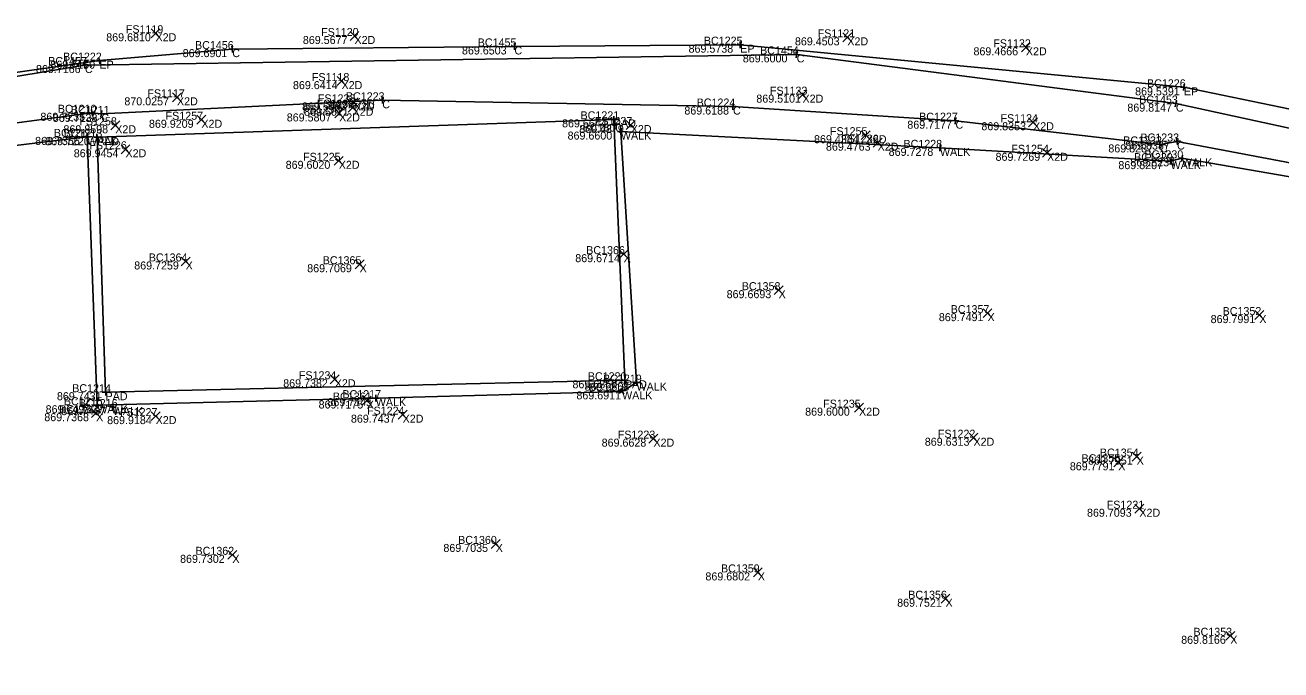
# Model space of a CAD drawing. Extents: x 1479425 to 1480294, y 379351 to 380102.
# Drawn here: x 1479629.1 to 1479638.52, y 379873.44 to 379878.28 of the extents above; entities that cross this region are included whole.
import ezdxf

# ---------------------------------------------------------------- set-up
doc = ezdxf.new("R2010")
doc.units = 0
for name, color, linetype in [('PV_X_Curb', 7, 'Continuous'), ('PV_X_Walk', 7, 'Continuous'), ('RD_X_Concrete_Pad', 7, 'Continuous'), ('SV_X_Random_Point', 7, 'Continuous'), ('SV_X_Shot_Marker', 7, 'Continuous'), ('SV_X_Text_Comment', 7, 'Continuous'), ('SV_X_Text_Elevation', 7, 'Continuous'), ('SV_X_Text_Name', 7, 'Continuous')]:
    doc.layers.add(name, color=color, linetype=linetype)

msp = doc.modelspace()

# ---------------------------------------------------------------- linework, layer by layer
at = {"layer": 'PV_X_Curb'}
for points in [[(1479547.645, 379857.8163), (1479566.743, 379862.6799), (1479585.84, 379867.6329), (1479595.941, 379870.2102), (1479610.1511, 379873.8057), (1479614.8317, 379874.9648), (1479619.4026, 379876.1566), (1479624.8139, 379877.3196), (1479629.6596, 379878.0099), (1479630.6556, 379878.0962), (1479632.7718, 379878.1163), (1479634.4649, 379878.1296), (1479637.7922, 379877.8099), (1479639.1613, 379877.5269), (1479644.7184, 379876.0341), (1479650.0207, 379873.0081)], [(1479674.4002, 379850.8088), (1479663.165, 379861.2618), (1479660.4814, 379863.897), (1479660.3417, 379864.0048), (1479659.4756, 379864.8615), (1479657.9728, 379866.276), (1479656.299, 379867.8605), (1479655.4781, 379868.4849), (1479655.3936, 379868.553), (1479653.3405, 379870.3718), (1479649.8028, 379873.0366), (1479644.8359, 379875.8815), (1479640.9714, 379876.9839), (1479637.7316, 379877.6879), (1479634.8886, 379878.0569), (1479629.5507, 379877.9769), (1479626.9417, 379877.5496), (1479624.927, 379877.2311), (1479623.2196, 379876.8713), (1479619.5522, 379875.9957), (1479615.007, 379874.7968)], [(1479547.62, 379857.3293), (1479567.188, 379862.296), (1479585.958, 379867.1036), (1479596.074, 379869.8004), (1479610.1997, 379873.3276), (1479614.9812, 379874.5289), (1479617.4646, 379875.192), (1479619.4347, 379875.7199), (1479619.5957, 379875.717), (1479622.3222, 379876.3413), (1479624.8041, 379876.8646), (1479627.2818, 379877.3077), (1479629.6031, 379877.6193), (1479629.6735, 379877.6107), (1479631.7805, 379877.7128), (1479634.4106, 379877.6659), (1479636.0794, 379877.5598), (1479637.6114, 379877.382), (1479637.7407, 379877.4038), (1479639.5316, 379877.066), (1479644.5411, 379875.6244), (1479649.735, 379872.6614)]]:
    msp.add_lwpolyline(points, dxfattribs=at)
at = {"layer": 'PV_X_Walk'}
msp.add_lwpolyline([(1479648.689, 379868.2743), (1479647.1434, 379869.696), (1479647.0829, 379869.7025), (1479645.8749, 379870.8123), (1479644.5568, 379872.0701), (1479644.4905, 379872.1256), (1479643.2259, 379873.2388), (1479641.9481, 379874.5109), (1479641.8756, 379874.5801), (1479640.4852, 379875.8117), (1479639.2266, 379877.0297), (1479637.7773, 379877.2778), (1479637.6922, 379877.2566), (1479635.9625, 379877.3562), (1479633.5699, 379877.4783), (1479633.687, 379875.5967), (1479633.579, 379875.5311), (1479631.7319, 379875.4802), (1479629.6435, 379875.4272), (1479629.5678, 379877.4383), (1479627.2312, 379877.1555), (1479624.9702, 379876.7386), (1479624.8804, 379876.715), (1479622.4184, 379876.2221)], dxfattribs=at)
at = {"layer": 'RD_X_Concrete_Pad'}
msp.add_lwpolyline([(1479629.6418, 379877.4358), (1479629.7055, 379875.5248), (1479633.5999, 379875.6143), (1479633.5176, 379877.57)], close=True, dxfattribs=at)
at = {"layer": 'SV_X_Random_Point'}
for p, q in [((1479630.0467, 379878.1818), (1479630.1133, 379878.2486)), ((1479630.0467, 379878.2486), (1479630.1133, 379878.1818)), ((1479631.5387, 379878.1614), (1479631.6053, 379878.2282)), ((1479631.5387, 379878.2282), (1479631.6053, 379878.1614)), ((1479635.2347, 379878.1512), (1479635.3013, 379878.218)), ((1479635.2347, 379878.218), (1479635.3013, 379878.1512)), ((1479636.5737, 379878.0765), (1479636.6403, 379878.1433)), ((1479636.5737, 379878.1433), (1479636.6403, 379878.0765)), ((1479631.4417, 379877.8231), (1479631.5083, 379877.8899)), ((1479631.4417, 379877.8899), (1479631.5083, 379877.8231)), ((1479630.2077, 379877.7017), (1479630.2743, 379877.7685)), ((1479630.2077, 379877.7685), (1479630.2743, 379877.7017)), ((1479634.8987, 379877.7217), (1479634.9653, 379877.7885)), ((1479634.8987, 379877.7885), (1479634.9653, 379877.7217)), ((1479631.4237, 379877.5809), (1479631.4903, 379877.6477)), ((1479631.4237, 379877.6477), (1479631.4903, 379877.5809)), ((1479631.5247, 379877.6236), (1479631.5913, 379877.6904)), ((1479631.5247, 379877.6904), (1479631.5913, 379877.6236)), ((1479631.5337, 379877.6636), (1479631.6003, 379877.7304)), ((1479631.5337, 379877.7304), (1479631.6003, 379877.6636)), ((1479629.7447, 379877.4922), (1479629.8113, 379877.559)), ((1479629.7447, 379877.559), (1479629.8113, 379877.4922)), ((1479630.3907, 379877.5333), (1479630.4573, 379877.6001)), ((1479630.3907, 379877.6001), (1479630.4573, 379877.5333)), ((1479633.6107, 379877.4939), (1479633.6773, 379877.5607)), ((1479633.6107, 379877.5607), (1479633.6773, 379877.4939)), ((1479636.6277, 379877.5149), (1479636.6943, 379877.5817)), ((1479636.6277, 379877.5817), (1479636.6943, 379877.5149)), ((1479635.3727, 379877.4177), (1479635.4393, 379877.4845)), ((1479635.3727, 379877.4845), (1479635.4393, 379877.4177)), ((1479629.8217, 379877.3123), (1479629.8883, 379877.3791)), ((1479629.8217, 379877.3791), (1479629.8883, 379877.3123)), ((1479635.4617, 379877.3618), (1479635.5283, 379877.4286)), ((1479635.4617, 379877.4286), (1479635.5283, 379877.3618)), ((1479631.4207, 379877.2258), (1479631.4873, 379877.2926)), ((1479631.4207, 379877.2926), (1479631.4873, 379877.2258)), ((1479636.7327, 379877.2857), (1479636.7993, 379877.3525)), ((1479636.7327, 379877.3525), (1479636.7993, 379877.2857)), ((1479630.2726, 379876.4713), (1479630.3392, 379876.5381)), ((1479630.2726, 379876.5381), (1479630.3392, 379876.4713)), ((1479631.5774, 379876.4505), (1479631.644, 379876.5173)), ((1479631.5774, 379876.5173), (1479631.644, 379876.4505)), ((1479633.5572, 379876.526), (1479633.6238, 379876.5928)), ((1479633.5572, 379876.5928), (1479633.6238, 379876.526)), ((1479634.7194, 379876.2561), (1479634.786, 379876.3229)), ((1479634.7194, 379876.3229), (1479634.786, 379876.2561)), ((1479636.2858, 379876.084), (1479636.3524, 379876.1508)), ((1479636.2858, 379876.1508), (1479636.3524, 379876.084)), ((1479638.3245, 379876.0694), (1479638.3911, 379876.1362)), ((1479638.3245, 379876.1362), (1479638.3911, 379876.0694)), ((1479631.3907, 379875.5884), (1479631.4573, 379875.6552)), ((1479631.3907, 379875.6552), (1479631.4573, 379875.5884)), ((1479631.6312, 379875.4292), (1479631.6978, 379875.496)), ((1479631.6312, 379875.496), (1479631.6978, 379875.4292)), ((1479629.6012, 379875.3342), (1479629.6678, 379875.401)), ((1479629.6012, 379875.401), (1479629.6678, 379875.3342)), ((1479631.8997, 379875.3229), (1479631.9663, 379875.3897)), ((1479631.8997, 379875.3897), (1479631.9663, 379875.3229)), ((1479635.3227, 379875.3755), (1479635.3893, 379875.4423)), ((1479635.3227, 379875.4423), (1479635.3893, 379875.3755)), ((1479630.0477, 379875.3121), (1479630.1143, 379875.3789)), ((1479630.0477, 379875.3789), (1479630.1143, 379875.3121)), ((1479633.7807, 379875.1434), (1479633.8473, 379875.2102)), ((1479633.7807, 379875.2102), (1479633.8473, 379875.1434)), ((1479636.1807, 379875.1501), (1479636.2473, 379875.2169)), ((1479636.1807, 379875.2169), (1479636.2473, 379875.1501)), ((1479637.2666, 379874.9663), (1479637.3332, 379875.0331)), ((1479637.2666, 379875.0331), (1479637.3332, 379874.9663)), ((1479637.4044, 379875.0089), (1479637.471, 379875.0757)), ((1479637.4044, 379875.0757), (1479637.471, 379875.0089)), ((1479637.4247, 379874.618), (1479637.4913, 379874.6848)), ((1479637.4247, 379874.6848), (1479637.4913, 379874.618)), ((1479632.5982, 379874.3542), (1479632.6648, 379874.421)), ((1479632.5982, 379874.421), (1479632.6648, 379874.3542)), ((1479630.623, 379874.2725), (1479630.6896, 379874.3393)), ((1479630.623, 379874.3393), (1479630.6896, 379874.2725)), ((1479634.5637, 379874.1407), (1479634.6303, 379874.2075)), ((1479634.5637, 379874.2075), (1479634.6303, 379874.1407)), ((1479635.971, 379873.9434), (1479636.0376, 379874.0102)), ((1479635.971, 379874.0102), (1479636.0376, 379873.9434)), ((1479638.1061, 379873.6656), (1479638.1727, 379873.7324)), ((1479638.1061, 379873.7324), (1479638.1727, 379873.6656))]:
    msp.add_line(p, q, dxfattribs=at)
at = {"layer": 'SV_X_Shot_Marker'}
for p, q in [((1479630.6534, 379878.1211), (1479630.6578, 379878.0713)), ((1479632.7468, 379878.1161), (1479632.7968, 379878.1166)), ((1479632.7716, 379878.1413), (1479632.772, 379878.0913)), ((1479632.7718, 379878.1163), (1479632.7718, 379878.1163)), ((1479634.4399, 379878.1294), (1479634.4899, 379878.1298)), ((1479634.4647, 379878.1546), (1479634.4651, 379878.1046)), ((1479634.4649, 379878.1296), (1479634.4649, 379878.1296)), ((1479629.6561, 379878.0347), (1479629.6631, 379877.9852)), ((1479630.6307, 379878.0941), (1479630.6805, 379878.0984)), ((1479630.6556, 379878.0962), (1479630.6556, 379878.0962)), ((1479634.9134, 379878.0537), (1479634.8638, 379878.0601)), ((1479634.8854, 379878.0321), (1479634.8918, 379878.0817)), ((1479634.8886, 379878.0569), (1479634.8886, 379878.0569)), ((1479629.5757, 379877.9773), (1479629.5257, 379877.9765)), ((1479629.5511, 379877.9519), (1479629.5503, 379878.0019)), ((1479629.5507, 379877.9769), (1479629.5507, 379877.9769)), ((1479629.6348, 379878.0064), (1479629.6843, 379878.0134)), ((1479629.6596, 379878.0099), (1479629.6596, 379878.0099)), ((1479637.7946, 379877.8348), (1479637.7898, 379877.785)), ((1479631.7793, 379877.7378), (1479631.7817, 379877.6878)), ((1479637.7673, 379877.8123), (1479637.8171, 379877.8075)), ((1479637.7922, 379877.8099), (1479637.7922, 379877.8099)), ((1479629.5998, 379877.6441), (1479629.6064, 379877.5945)), ((1479631.7555, 379877.7116), (1479631.8055, 379877.714)), ((1479631.7805, 379877.7128), (1479631.7805, 379877.7128)), ((1479634.3856, 379877.6664), (1479634.4356, 379877.6655)), ((1479634.411, 379877.6909), (1479634.4102, 379877.6409)), ((1479634.4106, 379877.6659), (1479634.4106, 379877.6659)), ((1479637.756, 379877.6826), (1479637.7072, 379877.6932)), ((1479637.7263, 379877.6635), (1479637.7369, 379877.7123)), ((1479637.7316, 379877.6879), (1479637.7316, 379877.6879)), ((1479629.5783, 379877.616), (1479629.6279, 379877.6226)), ((1479629.6031, 379877.6193), (1479629.6031, 379877.6193)), ((1479629.6487, 379877.6138), (1479629.6983, 379877.6077)), ((1479629.6765, 379877.6355), (1479629.6705, 379877.5859)), ((1479629.6735, 379877.6107), (1479629.6735, 379877.6107)), ((1479633.4926, 379877.569), (1479633.5426, 379877.5711)), ((1479633.5186, 379877.545), (1479633.5165, 379877.595)), ((1479633.5176, 379877.57), (1479633.5176, 379877.57)), ((1479636.0544, 379877.5614), (1479636.1043, 379877.5582)), ((1479636.081, 379877.5848), (1479636.0778, 379877.5349)), ((1479636.0794, 379877.5598), (1479636.0794, 379877.5598)), ((1479629.5687, 379877.4133), (1479629.5669, 379877.4633)), ((1479629.641, 379877.4608), (1479629.6426, 379877.4108)), ((1479633.5949, 379877.4771), (1479633.545, 379877.4796)), ((1479633.5687, 379877.4534), (1479633.5712, 379877.5033)), ((1479633.5699, 379877.4783), (1479633.5699, 379877.4783)), ((1479629.5428, 379877.4374), (1479629.5928, 379877.4393)), ((1479629.5678, 379877.4383), (1479629.5678, 379877.4383)), ((1479629.6668, 379877.4367), (1479629.6168, 379877.435)), ((1479629.6418, 379877.4358), (1479629.6418, 379877.4358)), ((1479635.9611, 379877.3313), (1479635.9639, 379877.3812)), ((1479637.5866, 379877.3849), (1479637.6362, 379877.3791)), ((1479637.6143, 379877.4069), (1479637.6085, 379877.3572)), ((1479637.6114, 379877.382), (1479637.6114, 379877.382)), ((1479637.716, 379877.3997), (1479637.7653, 379877.408)), ((1479637.7365, 379877.4285), (1479637.7449, 379877.3792)), ((1479637.7407, 379877.4038), (1479637.7407, 379877.4038)), ((1479635.9875, 379877.3548), (1479635.9375, 379877.3577)), ((1479635.9625, 379877.3562), (1479635.9625, 379877.3562)), ((1479637.6982, 379877.2324), (1479637.6862, 379877.2809)), ((1479637.8019, 379877.2736), (1479637.7527, 379877.282)), ((1479637.7731, 379877.2532), (1479637.7815, 379877.3025)), ((1479637.7773, 379877.2778), (1479637.7773, 379877.2778)), ((1479637.7165, 379877.2627), (1479637.6679, 379877.2506)), ((1479637.6922, 379877.2566), (1479637.6922, 379877.2566)), ((1479633.5749, 379875.6137), (1479633.6249, 379875.6149)), ((1479633.5993, 379875.6393), (1479633.6005, 379875.5893)), ((1479633.5999, 379875.6143), (1479633.5999, 379875.6143)), ((1479633.7119, 379875.5983), (1479633.662, 379875.5952)), ((1479633.6854, 379875.6217), (1479633.6885, 379875.5718)), ((1479633.687, 379875.5967), (1479633.687, 379875.5967)), ((1479629.7305, 379875.5257), (1479629.6805, 379875.524)), ((1479629.7047, 379875.5498), (1479629.7063, 379875.4998)), ((1479629.7055, 379875.5248), (1479629.7055, 379875.5248)), ((1479631.7569, 379875.4809), (1479631.7069, 379875.4795)), ((1479631.7326, 379875.4552), (1479631.7312, 379875.5052)), ((1479631.7319, 379875.4802), (1479631.7319, 379875.4802)), ((1479633.6004, 379875.5441), (1479633.5576, 379875.5181)), ((1479633.592, 379875.5098), (1479633.566, 379875.5525)), ((1479633.579, 379875.5311), (1479633.579, 379875.5311)), ((1479629.6685, 379875.4279), (1479629.6185, 379875.4266)), ((1479629.6441, 379875.4022), (1479629.6429, 379875.4522)), ((1479629.6435, 379875.4272), (1479629.6435, 379875.4272)), ((1479629.7348, 379875.4161), (1479629.7844, 379875.4101)), ((1479629.7626, 379875.4379), (1479629.7566, 379875.3883)), ((1479629.7596, 379875.4131), (1479629.7596, 379875.4131))]:
    msp.add_line(p, q, dxfattribs=at)

# ---------------------------------------------------------------- texts
at = {"layer": 'SV_X_Text_Comment'}
for s, p in [('X2D', (1479630.08, 379878.1552)), ('X2D', (1479631.572, 379878.1348)), ('C', (1479632.7718, 379878.0563)), ('EP', (1479634.4649, 379878.0696)), ('X2D', (1479635.268, 379878.1246)), ('C', (1479630.6556, 379878.0362)), ('C', (1479634.8886, 379877.9969)), ('X2D', (1479636.607, 379878.0499)), ('C', (1479629.5507, 379877.9169)), ('EP', (1479629.6596, 379877.9499)), ('X2D', (1479631.475, 379877.7965)), ('X2D', (1479634.932, 379877.6951)), ('EP', (1479637.7922, 379877.7499)), ('X2D', (1479630.241, 379877.6751)), ('X2D', (1479631.558, 379877.597)), ('X2D', (1479631.567, 379877.637)), ('C', (1479631.7805, 379877.6528)), ('C', (1479634.4106, 379877.6059)), ('C', (1479637.7316, 379877.6279)), ('C', (1479629.6031, 379877.5593)), ('C', (1479629.6735, 379877.5507)), ('X2D', (1479630.424, 379877.5067)), ('X2D', (1479631.457, 379877.5543)), ('PAD', (1479633.5176, 379877.51)), ('C', (1479636.0794, 379877.4998)), ('X2D', (1479636.661, 379877.4883)), ('X2D', (1479629.778, 379877.4656)), ('WALK', (1479633.5699, 379877.4183)), ('X2D', (1479633.644, 379877.4673)), ('WALK', (1479629.5678, 379877.3783)), ('PAD', (1479629.6418, 379877.3758)), ('X2D', (1479635.406, 379877.3911)), ('X2D', (1479635.495, 379877.3352)), ('C', (1479637.6114, 379877.322)), ('C', (1479637.7407, 379877.3438)), ('X2D', (1479629.855, 379877.2857)), ('WALK', (1479635.9625, 379877.2962)), ('X2D', (1479636.766, 379877.2591)), ('WALK', (1479637.7773, 379877.2178)), ('X2D', (1479631.454, 379877.1992)), ('WALK', (1479637.6922, 379877.1966)), ('X', (1479633.5905, 379876.4994)), ('X', (1479630.3059, 379876.4447)), ('X', (1479631.6107, 379876.4239)), ('X', (1479634.7527, 379876.2295)), ('X', (1479636.3191, 379876.0574)), ('X', (1479638.3578, 379876.0428)), ('X2D', (1479631.424, 379875.5618)), ('PAD', (1479633.5999, 379875.5543)), ('WALK', (1479633.687, 379875.5367)), ('PAD', (1479629.7055, 379875.4648)), ('WALK', (1479631.7319, 379875.4202)), ('WALK', (1479633.579, 379875.4711)), ('WALK', (1479629.6435, 379875.3672)), ('WALK', (1479629.7596, 379875.3531)), ('X', (1479631.6645, 379875.4026)), ('X2D', (1479635.356, 379875.3489)), ('X', (1479629.6345, 379875.3076)), ('X2D', (1479630.081, 379875.2855)), ('X2D', (1479631.933, 379875.2963)), ('X2D', (1479633.814, 379875.1168)), ('X2D', (1479636.214, 379875.1235)), ('X', (1479637.4377, 379874.9823)), ('X', (1479637.2999, 379874.9397)), ('X2D', (1479637.458, 379874.5914)), ('X', (1479632.6315, 379874.3276)), ('X', (1479630.6563, 379874.2459)), ('X', (1479634.597, 379874.1141)), ('X', (1479636.0043, 379873.9168)), ('X', (1479638.1394, 379873.639))]:
    msp.add_text(s, height=0.06, dxfattribs=at).set_placement(p)
at = {"layer": 'SV_X_Text_Elevation'}
for s, p in [('869.6810', (1479629.7106, 379878.1552)), ('869.5677', (1479631.1851, 379878.1348)), ('869.6503', (1479632.3783, 379878.0563)), ('869.5738', (1479634.0775, 379878.0696)), ('869.4503', (1479634.875, 379878.1246)), ('869.6901', (1479630.2837, 379878.0362)), ('869.6000', (1479634.4842, 379877.9969)), ('869.4666', (1479636.214, 379878.0499)), ('869.7166', (1479629.1837, 379877.9169)), ('869.7150', (1479629.2921, 379877.9499)), ('869.6414', (1479631.1108, 379877.7965)), ('869.5101', (1479634.5856, 379877.6951)), ('869.5391', (1479637.426, 379877.7499)), ('870.0257', (1479629.8465, 379877.6751)), ('869.5692', (1479631.1787, 379877.637)), ('869.5671', (1479631.1937, 379877.597)), ('869.6780', (1479631.3884, 379877.6528)), ('869.6188', (1479634.0459, 379877.6059)), ('869.8147', (1479637.3679, 379877.6279)), ('869.7235', (1479629.2171, 379877.5593)), ('869.7138', (1479629.3098, 379877.5507)), ('869.9209', (1479630.0309, 379877.5067)), ('869.5807', (1479631.0644, 379877.5543)), ('869.6644', (1479633.1288, 379877.51)), ('869.7177', (1479635.718, 379877.4998)), ('869.8353', (1479636.2731, 379877.4883)), ('869.8598', (1479629.3897, 379877.4656)), ('869.6600', (1479633.1703, 379877.4183)), ('869.4879', (1479633.2571, 379877.4673)), ('869.7356', (1479629.1771, 379877.3783)), ('869.7220', (1479629.2525, 379877.3758)), ('869.4384', (1479635.0181, 379877.3911)), ('869.4763', (1479635.1076, 379877.3352)), ('869.8287', (1479637.2254, 379877.322)), ('869.8337', (1479637.3519, 379877.3438)), ('869.9454', (1479629.4671, 379877.2857)), ('869.7278', (1479635.578, 379877.2962)), ('869.7269', (1479636.3796, 379877.2591)), ('869.8234', (1479637.3909, 379877.2178)), ('869.6020', (1479631.0562, 379877.1992)), ('869.8207', (1479637.3006, 379877.1966)), ('869.6714', (1479633.2277, 379876.4994)), ('869.7259', (1479629.9204, 379876.4447)), ('869.7069', (1479631.2176, 379876.4239)), ('869.6693', (1479634.363, 379876.2295)), ('869.7491', (1479635.9543, 379876.0574)), ('869.7991', (1479637.9925, 379876.0428)), ('869.7382', (1479631.0376, 379875.5618)), ('869.6850', (1479633.2068, 379875.5543)), ('869.6868', (1479633.2977, 379875.5367)), ('869.7431', (1479629.3407, 379875.4648)), ('869.7145', (1479631.3691, 379875.4202)), ('869.6911', (1479633.2364, 379875.4711)), ('869.7493', (1479629.2561, 379875.3672)), ('869.7467', (1479629.3722, 379875.3531)), ('869.7175', (1479631.3031, 379875.4026)), ('869.6000', (1479634.9516, 379875.3489)), ('869.7368', (1479629.2462, 379875.3076)), ('869.9184', (1479629.7173, 379875.2855)), ('869.7437', (1479631.5456, 379875.2963)), ('869.6628', (1479633.4257, 379875.1168)), ('869.6313', (1479635.8489, 379875.1235)), ('869.7951', (1479637.0734, 379874.9823)), ('869.7791', (1479636.9365, 379874.9397)), ('869.7093', (1479637.0654, 379874.5914)), ('869.7035', (1479632.2389, 379874.3276)), ('869.7302', (1479630.2642, 379874.2459)), ('869.6802', (1479634.2039, 379874.1141)), ('869.7521', (1479635.6418, 379873.9168)), ('869.8166', (1479637.7714, 379873.639))]:
    msp.add_text(s, height=0.06, dxfattribs=at).set_placement(p)
at = {"layer": 'SV_X_Text_Name'}
for s, p in [('FS1119', (1479629.8576, 379878.2152)), ('FS1120', (1479631.3222, 379878.1948)), ('FS1121', (1479635.0459, 379878.1846)), ('BC1456', (1479630.3764, 379878.0962)), ('BC1455', (1479632.4964, 379878.1163)), ('BC1225', (1479634.1919, 379878.1296)), ('BC1454', (1479634.6137, 379878.0569)), ('FS1122', (1479636.3628, 379878.1099)), ('BC1457', (1479629.2753, 379877.9769)), ('BC1222', (1479629.387, 379878.0099)), ('FS1118', (1479631.2526, 379877.8565)), ('BC1226', (1479637.5154, 379877.8099)), ('FS1117', (1479630.0191, 379877.7351)), ('FS1233', (1479631.2978, 379877.697)), ('BC1223', (1479631.5075, 379877.7128)), ('FS1123', (1479634.6874, 379877.7551)), ('BC1453', (1479637.4562, 379877.6879)), ('BC1210', (1479629.3476, 379877.6193)), ('BC1211', (1479629.4457, 379877.6107)), ('FS1256', (1479631.1849, 379877.6143)), ('FS1238', (1479631.2883, 379877.657)), ('BC1224', (1479634.138, 379877.6659)), ('FS1258', (1479629.5092, 379877.5256)), ('FS1257', (1479630.1557, 379877.5667)), ('BC1221', (1479633.2671, 379877.57)), ('FS1237', (1479633.3748, 379877.5273)), ('BC1227', (1479635.8064, 379877.5598)), ('FS1124', (1479636.4168, 379877.5483)), ('BC1212', (1479629.318, 379877.4383)), ('BC1213', (1479629.3915, 379877.4358)), ('BC1800', (1479633.2842, 379877.4783)), ('FS1255', (1479635.1377, 379877.4511)), ('FS1236', (1479635.222, 379877.3952)), ('BC1233', (1479637.4658, 379877.4038)), ('FS1226', (1479629.5839, 379877.3457)), ('BC1228', (1479635.689, 379877.3562)), ('FS1254', (1479636.4982, 379877.3191)), ('BC1232', (1479637.337, 379877.382)), ('FS1225', (1479631.1866, 379877.2592)), ('BC1229', (1479637.4187, 379877.2566)), ('BC1230', (1479637.4972, 379877.2778)), ('BC1366', (1479633.3099, 379876.5594)), ('BC1364', (1479630.0296, 379876.5047)), ('BC1365', (1479631.3339, 379876.4839)), ('BC1358', (1479634.4764, 379876.2895)), ('BC1357', (1479636.0432, 379876.1174)), ('BC1352', (1479638.0824, 379876.1028)), ('FS1234', (1479631.1552, 379875.6218)), ('BC1220', (1479633.3217, 379875.6143)), ('BC1214', (1479629.4557, 379875.5248)), ('BC1218', (1479633.3282, 379875.5311)), ('BC1219', (1479633.4362, 379875.5967)), ('BC1215', (1479629.3932, 379875.4272)), ('BC1361', (1479631.4103, 379875.4626)), ('BC1217', (1479631.4816, 379875.4802)), ('BC1363', (1479629.3577, 379875.3676)), ('BC1216', (1479629.5055, 379875.4131)), ('FS1227', (1479629.8136, 379875.3455)), ('FS1224', (1479631.6661, 379875.3563)), ('FS1235', (1479635.0868, 379875.4089)), ('FS1223', (1479633.5466, 379875.1768)), ('FS1222', (1479635.9471, 379875.1835)), ('BC1354', (1479637.1623, 379875.0423)), ('BC1355', (1479637.024, 379874.9997)), ('FS1221', (1479637.2132, 379874.6514)), ('BC1360', (1479632.3495, 379874.3876)), ('BC1362', (1479630.38, 379874.3059)), ('BC1359', (1479634.3207, 379874.1741)), ('BC1356', (1479635.7247, 379873.9768)), ('BC1353', (1479637.8635, 379873.699))]:
    msp.add_text(s, height=0.06, dxfattribs=at).set_placement(p)

doc.saveas('drawing.dxf')
